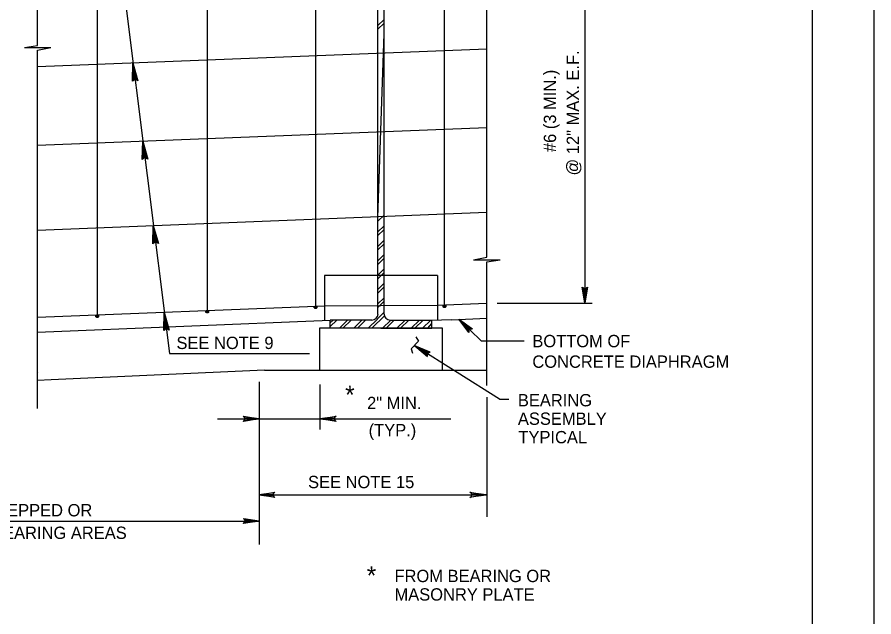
# Model space of a CAD drawing. Extents: x 640009 to 641706, y 298547 to 299735.
# Drawn here: x 641482.9 to 641691.5, y 299442.5 to 299588.5 of the extents above; entities that cross this region are included whole.
import ezdxf

# ---------------------------------------------------------------- set-up
doc = ezdxf.new("R2010")
doc.units = 0
doc.layers.add('1', color=7, linetype='Continuous')
doc.layers.add('PLT-BNDY', color=7, linetype='Continuous')

msp = doc.modelspace()

# ---------------------------------------------------------------- linework, layer by layer
at = {"layer": '1'}
for p, q in [((641676.47, 299720.17), (641676.47, 299156.17)), ((641676.47, 299720.17), (641676.47, 299156.17)), ((641586.99, 299518.22), (641586.99, 299643.72)), ((641555.62, 299517.71), (641555.62, 299642.6)), ((641502.49, 299515.64), (641502.49, 299640.22)), ((641529.24, 299516.87), (641529.24, 299641.6)), ((641621.12, 299621.1), (641621.12, 299518.87)), ((641506.19, 299616.62), (641519.99, 299506.6)), ((641487.87, 299581.6), (641487.87, 299606.58)), ((641597.24, 299530.08), (641597.24, 299606.1)), ((641570.74, 299516.21), (641570.74, 299593.22)), ((641570.74, 299516.21), (641570.74, 299593.22)), ((641572.24, 299516.21), (641572.24, 299593.22)), ((641572.24, 299516.21), (641572.24, 299593.22)), ((641484.74, 299581.1), (641487.87, 299581.6)), ((641484.74, 299581.1), (641491.12, 299581.1)), ((641487.87, 299580.45), (641491.12, 299581.1)), ((641487.87, 299576.48), (641597.24, 299580.83)), ((641487.87, 299493.21), (641487.87, 299580.45)), ((641487.99, 299581.1), (641487.99, 299581.1)), ((641487.87, 299557.32), (641597.24, 299561.67)), ((641487.87, 299536.69), (641597.24, 299541.04)), ((641593.99, 299529.46), (641597.24, 299530.08)), ((641593.99, 299529.46), (641600.49, 299529.46)), ((641597.24, 299528.96), (641600.49, 299529.46)), ((641597.24, 299498.83), (641597.24, 299528.96)), ((641557.72, 299525.65), (641557.72, 299514.65)), ((641585.26, 299525.65), (641557.72, 299525.65)), ((641585.26, 299525.65), (641585.26, 299514.77)), ((641585.26, 299518.39), (641597.24, 299518.87)), ((641599.74, 299518.87), (641622.87, 299518.87)), ((641487.87, 299515.45), (641557.72, 299518.27)), ((641557.72, 299518.27), (641585.26, 299518.39)), ((641487.87, 299511.83), (641559.12, 299514.71)), ((641569.24, 299514.71), (641559.12, 299514.71)), ((641559.12, 299512.83), (641559.12, 299514.71)), ((641569.24, 299514.71), (641559.12, 299514.71)), ((641559.12, 299512.83), (641559.12, 299514.71)), ((641573.74, 299514.71), (641583.87, 299514.71)), ((641573.74, 299514.71), (641583.87, 299514.71)), ((641583.87, 299514.71), (641588.61, 299514.9)), ((641583.87, 299512.83), (641583.87, 299514.71)), ((641583.87, 299512.83), (641583.87, 299514.71)), ((641588.62, 299514.83), (641597.24, 299515.21)), ((641595.91, 299509.67), (641590.5, 299514.91)), ((641583.87, 299512.83), (641559.12, 299512.83)), ((641571.49, 299512.83), (641559.12, 299512.83)), ((641571.49, 299512.83), (641583.87, 299512.83)), ((641600.37, 299495.47), (641579.76, 299508.47)), ((641595.91, 299509.67), (641606.31, 299509.67)), ((641519.99, 299506.6), (641554.09, 299506.6)), ((641543.12, 299502.58), (641491.24, 299500.21)), ((641543.12, 299502.58), (641556.49, 299502.58)), ((641556.49, 299502.58), (641586.62, 299502.58)), ((641556.49, 299502.58), (641586.49, 299502.58)), ((641586.62, 299502.58), (641597.12, 299502.58)), ((641491.24, 299500.21), (641487.87, 299500.06)), ((641541.87, 299499.71), (641541.87, 299460.08)), ((641556.62, 299499.08), (641556.62, 299488.08)), ((641597.24, 299495.96), (641597.24, 299466.83)), ((641600.37, 299495.47), (641602.62, 299495.47)), ((641531.74, 299490.71), (641559.37, 299490.71)), ((641556.37, 299490.71), (641588.53, 299490.71)), ((641543.24, 299472.21), (641597.12, 299472.21)), ((641420.24, 299465.83), (641541.87, 299465.83))]:
    msp.add_line(p, q, dxfattribs=at)
for points in [[(641570.74, 299586.47), (641572.24, 299587.97)], [(641570.74, 299585.6), (641572.24, 299587.1)], [(641570.74, 299539.71), (641572.24, 299584.47)], [(641511.21, 299573.08), (641511.41, 299573.26), (641511.11, 299577.41), (641511.21, 299573.08), (641511.01, 299572.91), (641511.11, 299577.41), (641511.79, 299573.42), (641512.16, 299573.21), (641511.11, 299577.41), (641512.33, 299573.01), (641512.16, 299573.21)], [(641513.6, 299554.01), (641513.8, 299554.18), (641513.5, 299558.34), (641513.6, 299554.01), (641513.4, 299553.83), (641513.5, 299558.34), (641514.19, 299554.35), (641514.55, 299554.14), (641513.5, 299558.34), (641514.72, 299553.94), (641514.55, 299554.14)], [(641570.74, 299538.83), (641572.24, 299540.33)], [(641516.17, 299533.48), (641516.37, 299533.66), (641516.07, 299537.81), (641516.17, 299533.48), (641515.98, 299533.3), (641516.07, 299537.81), (641516.76, 299533.82), (641517.12, 299533.61), (641516.07, 299537.81), (641517.3, 299533.41), (641517.12, 299533.61)], [(641570.74, 299536.21), (641572.24, 299537.71)], [(641570.74, 299535.33), (641572.24, 299536.83)], [(641570.74, 299532.71), (641572.24, 299534.21)], [(641570.74, 299531.83), (641572.24, 299533.33)], [(641570.74, 299529.21), (641572.24, 299530.71)], [(641570.74, 299528.33), (641572.24, 299529.83)], [(641570.74, 299525.71), (641572.24, 299527.21)], [(641570.74, 299524.83), (641572.24, 299526.33)], [(641570.74, 299522.21), (641572.24, 299523.71)], [(641570.74, 299521.33), (641572.24, 299522.83)], [(641621.62, 299522.62), (641621.37, 299522.49), (641621.12, 299518.87), (641621.62, 299522.62), (641621.74, 299522.74), (641621.12, 299518.87), (641620.99, 299522.49), (641620.74, 299522.62), (641621.12, 299518.87), (641620.49, 299522.74), (641620.74, 299522.62)], [(641570.74, 299518.71), (641572.24, 299520.21)], [(641570.74, 299517.83), (641572.24, 299519.33)], [(641518.82, 299512.37), (641519.02, 299512.54), (641518.72, 299516.7), (641518.82, 299512.37), (641518.62, 299512.19), (641518.72, 299516.7), (641519.41, 299512.71), (641519.77, 299512.5), (641518.72, 299516.7), (641519.94, 299512.3), (641519.77, 299512.5)], [(641529.24, 299516.75), (641529.24, 299516.87), (641529.24, 299516.87), (641529.24, 299516.87), (641529.37, 299516.87), (641529.37, 299516.75), (641529.37, 299516.75), (641529.24, 299516.62), (641529.24, 299516.62), (641529.12, 299516.62), (641529.12, 299516.75), (641529.12, 299516.87), (641529.12, 299516.87), (641529.12, 299517), (641529.24, 299517), (641529.37, 299517), (641529.37, 299516.87), (641529.49, 299516.75), (641529.49, 299516.62), (641529.37, 299516.62), (641529.24, 299516.5), (641529.12, 299516.5), (641528.99, 299516.62), (641528.99, 299516.75), (641528.99, 299516.87), (641528.99, 299517), (641529.12, 299517), (641529.24, 299517), (641529.37, 299517), (641529.49, 299517), (641529.49, 299517), (641529.49, 299516.87), (641529.49, 299516.75), (641529.49, 299516.62), (641529.49, 299516.62), (641529.37, 299516.5), (641529.37, 299516.5), (641529.24, 299516.5), (641529.12, 299516.5), (641528.99, 299516.5), (641528.99, 299516.62), (641528.87, 299516.62), (641528.87, 299516.75), (641528.87, 299516.87), (641528.87, 299516.87), (641528.99, 299517), (641528.99, 299517), (641529.12, 299517.12), (641529.24, 299517.12), (641529.37, 299517.12), (641529.37, 299517), (641529.24, 299516.75)], [(641555.62, 299517.83), (641555.62, 299517.96), (641555.62, 299517.96), (641555.62, 299517.96), (641555.74, 299517.96), (641555.74, 299517.83), (641555.74, 299517.83), (641555.62, 299517.71), (641555.62, 299517.71), (641555.49, 299517.71), (641555.49, 299517.83), (641555.49, 299517.96), (641555.49, 299517.96), (641555.49, 299518.08), (641555.62, 299518.08), (641555.74, 299518.08), (641555.74, 299517.96), (641555.87, 299517.83), (641555.87, 299517.71), (641555.74, 299517.71), (641555.62, 299517.58), (641555.49, 299517.58), (641555.37, 299517.71), (641555.37, 299517.83), (641555.37, 299517.96), (641555.37, 299518.08), (641555.49, 299518.08), (641555.62, 299518.08), (641555.74, 299518.08), (641555.87, 299518.08), (641555.87, 299518.08), (641555.87, 299517.96), (641555.87, 299517.83), (641555.87, 299517.71), (641555.87, 299517.71), (641555.74, 299517.58), (641555.74, 299517.58), (641555.62, 299517.58), (641555.49, 299517.58), (641555.37, 299517.58), (641555.37, 299517.71), (641555.24, 299517.71), (641555.24, 299517.83), (641555.24, 299517.96), (641555.24, 299517.96), (641555.37, 299518.08), (641555.37, 299518.08), (641555.49, 299518.21), (641555.62, 299518.21), (641555.74, 299518.21), (641555.74, 299518.08), (641555.62, 299517.83)], [(641570.62, 299515.08), (641572.24, 299516.71)], [(641586.99, 299518.1), (641586.99, 299518.22), (641586.99, 299518.22), (641586.99, 299518.22), (641587.12, 299518.22), (641587.12, 299518.1), (641587.12, 299518.1), (641586.99, 299517.97), (641586.99, 299517.97), (641586.87, 299517.97), (641586.87, 299518.1), (641586.87, 299518.22), (641586.87, 299518.22), (641586.87, 299518.35), (641586.99, 299518.35), (641587.12, 299518.35), (641587.12, 299518.22), (641587.24, 299518.1), (641587.24, 299517.97), (641587.12, 299517.97), (641586.99, 299517.85), (641586.87, 299517.85), (641586.74, 299517.97), (641586.74, 299518.1), (641586.74, 299518.22), (641586.74, 299518.35), (641586.87, 299518.35), (641586.99, 299518.35), (641587.12, 299518.35), (641587.24, 299518.35), (641587.24, 299518.35), (641587.24, 299518.22), (641587.24, 299518.1), (641587.24, 299517.97), (641587.24, 299517.97), (641587.12, 299517.85), (641587.12, 299517.85), (641586.99, 299517.85), (641586.87, 299517.85), (641586.74, 299517.85), (641586.74, 299517.97), (641586.62, 299517.97), (641586.62, 299518.1), (641586.62, 299518.22), (641586.62, 299518.22), (641586.74, 299518.35), (641586.74, 299518.35), (641586.87, 299518.47), (641586.99, 299518.47), (641587.12, 299518.47), (641587.12, 299518.35), (641586.99, 299518.1)], [(641502.49, 299515.64), (641502.49, 299515.77), (641502.49, 299515.77), (641502.49, 299515.77), (641502.62, 299515.77), (641502.62, 299515.64), (641502.62, 299515.64), (641502.49, 299515.52), (641502.49, 299515.52), (641502.37, 299515.52), (641502.37, 299515.64), (641502.37, 299515.77), (641502.37, 299515.77), (641502.37, 299515.89), (641502.49, 299515.89), (641502.62, 299515.89), (641502.62, 299515.77), (641502.74, 299515.64), (641502.74, 299515.52), (641502.62, 299515.52), (641502.49, 299515.39), (641502.37, 299515.39), (641502.24, 299515.52), (641502.24, 299515.64), (641502.24, 299515.77), (641502.24, 299515.89), (641502.37, 299515.89), (641502.49, 299515.89), (641502.62, 299515.89), (641502.74, 299515.89), (641502.74, 299515.89), (641502.74, 299515.77), (641502.74, 299515.64), (641502.74, 299515.52), (641502.74, 299515.52), (641502.62, 299515.39), (641502.62, 299515.39), (641502.49, 299515.39), (641502.37, 299515.39), (641502.24, 299515.39), (641502.24, 299515.52), (641502.12, 299515.52), (641502.12, 299515.64), (641502.12, 299515.77), (641502.12, 299515.77), (641502.24, 299515.89), (641502.24, 299515.89), (641502.37, 299516.02), (641502.49, 299516.02), (641502.62, 299516.02), (641502.62, 299515.89), (641502.49, 299515.64)], [(641559.12, 299513.21), (641560.74, 299514.71)], [(641559.12, 299514.08), (641559.87, 299514.71)], [(641561.37, 299512.83), (641563.37, 299514.71)], [(641562.24, 299512.83), (641564.24, 299514.71)], [(641564.87, 299512.83), (641566.87, 299514.71)], [(641565.74, 299512.83), (641567.74, 299514.71)], [(641568.37, 299512.83), (641570.62, 299514.96)], [(641569.24, 299512.83), (641572.37, 299515.83)], [(641571.87, 299512.83), (641573.87, 299514.71)], [(641572.74, 299512.83), (641574.74, 299514.71)], [(641575.37, 299512.83), (641577.37, 299514.71)], [(641576.24, 299512.83), (641578.24, 299514.71)], [(641578.87, 299512.83), (641580.87, 299514.71)], [(641579.74, 299512.83), (641581.74, 299514.71)], [(641581.62, 299512.83), (641583.62, 299514.71)], [(641592.84, 299511.98), (641592.98, 299512.22), (641590.5, 299514.91), (641592.84, 299511.98), (641592.88, 299511.7), (641590.5, 299514.91), (641593.22, 299512.54), (641593.59, 299512.65), (641590.5, 299514.91), (641593.77, 299512.62), (641593.59, 299512.65)], [(641582.87, 299512.83), (641583.87, 299513.96)], [(641579.99, 299510.71), (641580.65, 299509.59), (641578.84, 299507.74), (641579.17, 299506.73)], [(641583.18, 299506.91), (641582.97, 299506.72), (641579.76, 299508.47), (641583.18, 299506.91), (641583.45, 299506.94), (641579.76, 299508.47), (641582.72, 299506.42), (641582.71, 299506.02), (641579.76, 299508.47), (641582.78, 299505.86), (641582.71, 299506.02)], [(641583.18, 299506.91), (641582.97, 299506.72), (641579.76, 299508.47), (641583.18, 299506.91), (641583.45, 299506.94), (641579.76, 299508.47), (641582.72, 299506.42), (641582.71, 299506.02), (641579.76, 299508.47), (641582.78, 299505.86), (641582.71, 299506.02)], [(641487.87, 299501.95), (641487.99, 299502.08)], [(641586.37, 299502.58), (641586.49, 299502.58)], [(641538.12, 299491.21), (641538.24, 299490.96), (641541.87, 299490.71), (641538.12, 299491.21), (641537.99, 299491.33), (641541.87, 299490.71), (641538.24, 299490.58), (641538.12, 299490.33), (641541.87, 299490.71), (641537.99, 299490.08), (641538.12, 299490.33)], [(641560.37, 299490.33), (641560.24, 299490.58), (641556.62, 299490.71), (641560.37, 299490.33), (641560.62, 299490.08), (641556.62, 299490.71), (641560.24, 299490.96), (641560.37, 299491.21), (641556.62, 299490.71), (641560.62, 299491.33), (641560.37, 299491.21)], [(641545.49, 299471.71), (641545.37, 299471.96), (641541.74, 299472.21), (641545.49, 299471.71), (641545.62, 299471.58), (641541.74, 299472.21), (641545.24, 299472.33), (641545.49, 299472.71), (641541.74, 299472.21), (641545.62, 299472.83), (641545.49, 299472.71)], [(641593.37, 299472.71), (641593.49, 299472.46), (641597.12, 299472.21), (641593.37, 299472.71), (641593.12, 299472.83), (641597.12, 299472.21), (641593.49, 299472.08), (641593.37, 299471.71), (641597.12, 299472.21), (641593.12, 299471.58), (641593.37, 299471.71)], [(641538.12, 299466.33), (641538.24, 299466.08), (641541.87, 299465.83), (641538.12, 299466.33), (641537.99, 299466.46), (641541.87, 299465.83), (641538.24, 299465.71), (641538.12, 299465.46), (641541.87, 299465.83), (641537.99, 299465.21), (641538.12, 299465.46)]]:
    msp.add_lwpolyline(points, dxfattribs=at)
msp.add_lwpolyline([(641556.49, 299512.83), (641556.49, 299502.58), (641586.49, 299502.58), (641586.49, 299512.83)], close=True, dxfattribs=at)
for centre, start, end in [((641569.29, 299516.24), 270, 0), ((641569.29, 299516.24), 270, 0), ((641573.75, 299516.24), 180, 270), ((641573.75, 299516.24), 180, 270)]:
    msp.add_arc(centre, 1.49, start, end, dxfattribs=at)
at = {"layer": 'PLT-BNDY'}
msp.add_lwpolyline([(640850.47, 299735.17), (641691.47, 299735.17), (641691.47, 299141.17), (640850.47, 299141.17)], close=True, dxfattribs=at)

# ---------------------------------------------------------------- texts
at = {"layer": '1'}
for s, p in [('@ 12" MAX. E.F.', (641619.69, 299549.97)), ('#6 (3 MIN.)', (641614.11, 299555.67))]:
    msp.add_text(s, height=3, rotation=90, dxfattribs=at).set_placement(p)
for s, height, p in [('SEE NOTE 9', 3, (641521.71, 299507.71)), ('BOTTOM OF', 3, (641608.34, 299508.15)), ('CONCRETE DIAPHRAGM', 3, (641608.34, 299503.14)), ('*', 4.46, (641562.77, 299494.35)), ('2" MIN.', 3, (641568.11, 299493.07)), ('BEARING', 3, (641604.82, 299493.75)), ('ASSEMBLY', 3, (641604.82, 299489.25)), ('(TYP.)', 3, (641568.49, 299486.46)), ('TYPICAL', 3, (641604.94, 299484.75)), ('SEE NOTE 15', 3, (641553.74, 299473.83)), ('BRIDGE SEAT-STEPPED OR', 3, (641447.06, 299466.96)), ('SLOPED BETWEEN BEARING AREAS', 3, (641438.49, 299461.46)), ('*', 4.46, (641568.03, 299450.33)), ('FROM BEARING OR', 3, (641574.78, 299450.95)), ('MASONRY PLATE', 3, (641574.78, 299446.45))]:
    msp.add_text(s, height=height, dxfattribs=at).set_placement(p)

doc.saveas('drawing.dxf')
